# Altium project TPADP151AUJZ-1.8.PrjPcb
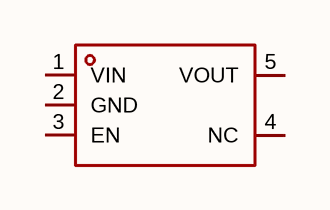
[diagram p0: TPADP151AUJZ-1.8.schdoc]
1 sheet, 1 parts. Net scope: global (net labels, ports and power ports of the same name join across sheets).

## Sheet TPADP151AUJZ-1.8.schdoc
size 127 x 101 mm

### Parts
U?  tpadp151aujz-1.8  [SOT-23-5_L2.9-W1.6-P0.95-LS2.8-BR]  (value not drawn)

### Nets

Not connected (* = marked no-connect by the designer): U? 1(VIN) 2(GND) 3(EN) 4(NC) 5(VOUT)

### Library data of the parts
U? = tpadp151aujz-1.8: 输出极性:正极;工作电压:5.5V;输出电压:1.8V;输出电流:200mA;电源纹波抑制比(PSRR):70dB@(1kHz);输出类型:固定;; Manufacturer: TECH PUBLIC(台舟); AddInBom: yes; ModelId: 7ba65df16e7b4570af156e925f9c37fe; ModelTransform: 114.173,114.173,0,90,0,0,0,0,0; Output Configuration: 正极; Voltage - Supply: 5.5V; Output Voltage: 1.8V; Output Current: 200mA; Voltage Dropout: 160mV@(200mA); standby current: 10uA; Output Type: 固定; Number of Outputs: 1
